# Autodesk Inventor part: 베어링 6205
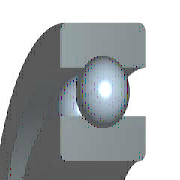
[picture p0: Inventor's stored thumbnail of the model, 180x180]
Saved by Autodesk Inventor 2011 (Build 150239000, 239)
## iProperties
Created: 2009-02
Part Number: 베어링 6205
Material: 강, 연강
Description: 깊은 그루브 볼 베어링
Document SubType Name: Modeling
Standard: KS B 2023
Designer: SeoGD™[esajin.kr]
Standards Organization: KS
Language: ko-KR
Size Designation: 6205 - 25 x 52 x 15
Categories: <MemberInstance><Categories><Category DisplayName="샤프트 부품" InternalName="7f7aeb1f-a693-4053-b835-cee3144e0d98" Mnemonic="SHFT"><Category DisplayName="베어링" Inter
Density: 1 g/cm^3
IsCustomPart: 1
Author: SeoGD™[esajin.kr]
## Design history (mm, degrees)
revolve "본체" stored, may be unused: angle "d6" = 90 deg
revolve "볼" stored, may be unused: angle "d7" = 90 deg
pattern_circular "IDS_ARRAYBALL[SIMPL:T]" dims angle "d3" = 360 deg
body "Solid1"
sketch "스케치" dims "d0" = 7.02 (= -0.26 x WD + 0.26 x BD)
  geometry: L1 (3.99, 19.25)-(11.01, 19.25); L2 (7.5, 19.25)-(7.5, 15.74); L3 (7.5, 19.25)-(7.5, 22.76); L4 (4.892, 16.901)-(0, 16.901); L5 (0, 12.5)-(15, 12.5); L6 (4.892, 21.599)-(0, 21.599); L7 (0, 26)-(15, 26); L8 (15, 12.5)-(15, 16.901); L9 (10.108, 16.901)-(15, 16.901); L10 (10.108, 21.599)-(15, 21.599); L11 (15, 26)-(15, 21.599); L12 (-1.4, 0)-(8.4, 0) reference; L13 (0, -0.3)-(0, 5.3) reference
  constraints: 22 end point, 4 point on line, 2 collinear, 2 perpendicular, 2 symmetric about line, 1 midpoint, 1 parallel, 14 other
  dimensions: "d9" = 25 diameter of L5 L12 (= WD); "d11" = 52 diameter of L7 L12 (= BD); "d12" = 15 distance between parallel lines of L8 L13 (= KB); "d13" = 33.802 diameter of L9 L12 (= 0.326 x BD + 0.674 x WD)
fillet "모깎기1" dims "d1" = 1 (= KRS)
other parameters: "WD" = 25 [user parameter; used in 5 equation terms], "BD" = 52 [user parameter; used in 5 equation terms], "KB" = 15 [user parameter; used in 1 equation term], "KRS" = 1 [user parameter; used in 1 equation term], "d4" = 0, "d5" = 0, "d8" = 0, "d14" = 0, "d15" = 0, "BBA" = 0 [user parameter], "BC0" = 7800000 [user parameter], "BC" = 1.4e+07 [user parameter], "BR" = 26 (= 0.5 x BD) [user parameter], "WR" = 12.5 (= 0.5 x WD) [user parameter]
